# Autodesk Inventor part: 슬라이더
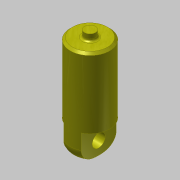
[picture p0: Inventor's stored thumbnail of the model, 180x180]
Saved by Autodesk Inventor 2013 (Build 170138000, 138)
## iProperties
Created: 2016-08
Part Number: 슬라이더
Material: 강철, 탄소
Document SubType Name: Modeling
Designer: mduedu
Density: 7.87 g/cm^3
Mass: 75.7926 g
Surface Area: 29.7311 cm^2
Volume: 9.63057 cm^3
Author: mduedu
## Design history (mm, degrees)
sketch "스케치1"
  geometry: C1 r 9 at (0, 0); 1 further point
  constraints: 1 centre point, 1 coincident
  dimensions: "d0" = 18 diameter of C1
extrude "돌출1" new body sketch "스케치1" distance "d1" = 45; taper "d2" = 0 deg
fillet "모깎기1" dims "d21" = 6
sketch "스케치6"
  geometry: L1 (9, 6)-(9, 45) reference; L2 (-9, 6)-(-9, 45) reference; L3 (9, 45)-(-9, 45) reference; L4 (0, 45)-(0, 0); L5 (9, 13)-(4, 13); L6 (4, 13)-(4, 0); L7 (4, 0)-(9, 0); L8 (9, 0)-(9, 13); L9 (-9, 13)-(-4, 13); L10 (-4, 13)-(-4, 0); L11 (-4, 0)-(-9, 0); L12 (-9, 0)-(-9, 13)
  constraints: 18 end point, 4 symmetric about line, 2 parallel, 2 perpendicular, 1 horizontal, 1 horizontal alignment, 1 midpoint, 1 point on line
  dimensions: "d22" = 13 distance of L7.end L5.start; "d24" = 4 distance between parallel lines of L6 L4
extrude "돌출5" cut sketch "스케치6" stored distance "d25" = 8; taper "d26" = 0 deg
sketch "스케치8"
  geometry: C1 r 3 at (6, 0); 1 further point
  constraints: 1 centre point, 1 horizontal alignment
  dimensions: "d27" = 6 diameter of C1; "d28" = 6 distance of point (0, 0) C1.centre
extrude "돌출6" cut sketch "스케치8" stored distance "d29" = 8; taper "d30" = 0 deg
chamfer "모따기2" distance "d43" = 1; stored, may be unused: second distance "d44" = 2, angle "d45" = 30 deg
sketch "스케치9"
  geometry: C1 r 2.5 at (0, 0); 1 further point
  constraints: 1 centre point, 1 coincident
  dimensions: "d47" = 5 diameter of C1
extrude "돌출7" join sketch "스케치9" distance "d48" = 3; taper "d49" = 0 deg
fillet "모깎기2" dims "d50" = 1
node "솔리드1"
